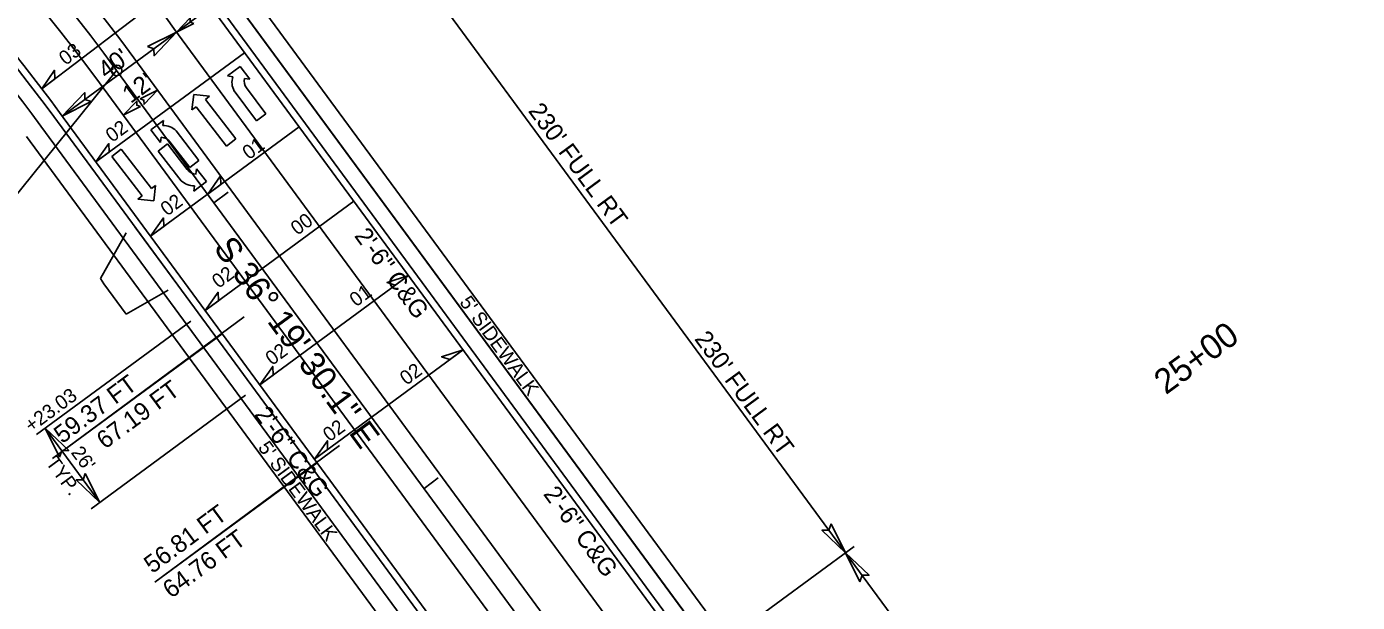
# Model space of a CAD drawing. Extents: x 1762196 to 1766326, y 709922 to 713142.
# Drawn here: x 1763337.1 to 1763712.3, y 712228.7 to 712391.1 of the extents above; entities that cross this region are included whole.
import ezdxf

# ---------------------------------------------------------------- set-up
doc = ezdxf.new("R2010")
doc.units = 0
for name, color, linetype in [('Old_Level_3', 7, 'Continuous'), ('Old_Level_30', 7, 'Continuous'), ('Pattern 1', 7, 'Continuous'), ('Pattern 2', 7, 'Continuous'), ('Pattern 4', 7, 'Continuous'), ('Prop Conc 2ft 6in Curb and Gutter', 7, 'Continuous'), ('Prop Dimension', 7, 'Continuous'), ('Prop EOT', 7, 'Continuous'), ('Prop Horizontal Alignment', 7, 'Continuous'), ('Prop Horizontal Alignment Direction Label', 7, 'Continuous'), ('Prop Horizontal Alignment Station Label', 7, 'Continuous'), ('Prop Horizontal Alignment Tick Label', 7, 'Continuous'), ('Prop Horizontal Alignment Tick Small', 7, 'Continuous'), ('Prop Lane Arrow CELL', 7, 'Continuous'), ('Prop Lane Lines', 7, 'Continuous'), ('Prop Superelevation  Arrow CELL', 7, 'Continuous'), ('Prop Superelevation Label', 7, 'Continuous'), ('Prop Terminator CELL', 7, 'Continuous')]:
    doc.layers.add(name, color=color, linetype=linetype)

msp = doc.modelspace()

# ---------------------------------------------------------------- linework, layer by layer
at = {"layer": 'Old_Level_3'}
for p, q in [((1763357.91, 712320.04), (1763365.16, 712332.88)), ((1763358.84, 712318.59), (1763357.91, 712320.04)), ((1763365.19, 712309.96), (1763358.84, 712318.59)), ((1763377.03, 712316.74), (1763365.19, 712309.96))]:
    msp.add_line(p, q, dxfattribs=at)
at = {"layer": 'Old_Level_30'}
for p, q in [((1763398.44, 712309.25), (1763344.42, 712269.29)), ((1763392.26, 712304.46), (1763344.42, 712269.29)), ((1763425.28, 712272.97), (1763373.22, 712234.45)), ((1763418.99, 712268.11), (1763373.22, 712234.45))]:
    msp.add_line(p, q, dxfattribs=at)
at = {"layer": 'Pattern 1'}
for p, q in [((1763534.54, 712218.15), (1763397.52, 712404.5)), ((1763845.53, 711677), (1763341.12, 712363.03)), ((1763337.1, 712360.07), (1763843.84, 711670.85))]:
    msp.add_line(p, q, dxfattribs=at)
msp.add_lwpolyline([(1763397.52, 712404.5), (1763393.49, 712401.54), (1763530.51, 712215.18)], dxfattribs=at)
msp.add_arc((1762933.05, 712063), 506.5, 36.325, 67.1495, dxfattribs=at)
at = {"layer": 'Pattern 2'}
for p, q in [((1763393.49, 712401.54), (1763530.51, 712215.18)), ((1763534.54, 712218.15), (1763397.52, 712404.5)), ((1763341.12, 712363.03), (1763845.53, 711677)), ((1763337.1, 712360.07), (1763843.84, 711670.85))]:
    msp.add_line(p, q, dxfattribs=at)
msp.add_arc((1762933.05, 712063), 506.5, 36.325, 67.1495, dxfattribs=at)
at = {"layer": 'Pattern 4'}
msp.add_line((1763379.44, 712318.51), (1763367.57, 712334.66), dxfattribs=at)
at = {"layer": 'Prop Conc 2ft 6in Curb and Gutter'}
for p, q in [((1763389.87, 712398.87), (1763526.88, 712212.52)), ((1763344.75, 712365.7), (1763842.1, 711689.26))]:
    msp.add_line(p, q, dxfattribs=at)
msp.add_arc((1762933.05, 712063), 511, 36.325, 65.7844, dxfattribs=at)
at = {"layer": 'Prop Dimension'}
for p, q in [((1763431.73, 712428.03), (1763567.97, 712242.73)), ((1763389.03, 712396.64), (1763379.36, 712389.53)), ((1763379.36, 712389.53), (1763347.13, 712365.84)), ((1763570.39, 712244.51), (1763527.69, 712213.11)), ((1763567.97, 712242.73), (1763627.21, 712162.16))]:
    msp.add_line(p, q, dxfattribs=at)
at = {"layer": 'Prop EOT'}
for p, q in [((1763388.26, 712397.69), (1763525.27, 712211.33)), ((1763346.36, 712366.89), (1763843.71, 711690.45))]:
    msp.add_line(p, q, dxfattribs=at)
msp.add_arc((1762933.05, 712063), 513, 36.325, 65.7844, dxfattribs=at)
at = {"layer": 'Prop Horizontal Alignment'}
msp.add_line((1763362.47, 712378.73), (1764087.96, 711392.01), dxfattribs=at)
msp.add_arc((1762933.05, 712063), 533, 36.325, 77.7598, dxfattribs=at)
at = {"layer": 'Prop Horizontal Alignment Station Label'}
msp.add_line((1763362.47, 712378.73), (1763237.09, 712223.4), dxfattribs=at)
msp.add_circle((1763362.47, 712378.73), 1.5, dxfattribs=at)
at = {"layer": 'Prop Horizontal Alignment Tick Small'}
for p, q in [((1763389.9, 712341.43), (1763393.93, 712344.39)), ((1763449.14, 712260.86), (1763453.17, 712263.82))]:
    msp.add_line(p, q, dxfattribs=at)
at = {"layer": 'Prop Lane Arrow CELL'}
for p, q in [((1763393.77, 712377.15), (1763397.26, 712379.83)), ((1763397.26, 712379.83), (1763399.99, 712376.25)), ((1763395.24, 712376.94), (1763393.77, 712377.15)), ((1763399.99, 712376.25), (1763398.52, 712376.47)), ((1763383.69, 712367.59), (1763384.22, 712371.97)), ((1763384.22, 712371.97), (1763388.68, 712371.43)), ((1763401.94, 712364.47), (1763395.62, 712372.92)), ((1763399.1, 712373.78), (1763404.58, 712366.45)), ((1763384.88, 712368.5), (1763383.69, 712367.59)), ((1763393.43, 712357.41), (1763384.88, 712368.5)), ((1763388.68, 712371.43), (1763387.49, 712370.52)), ((1763387.49, 712370.52), (1763396.04, 712359.43)), ((1763375.67, 712364.63), (1763372.16, 712361.98)), ((1763375.48, 712363.16), (1763375.67, 712364.63)), ((1763404.58, 712366.45), (1763401.94, 712364.47)), ((1763372.16, 712361.98), (1763374.87, 712358.39)), ((1763385.69, 712353.35), (1763379.25, 712361.71)), ((1763376.81, 712358), (1763374.2, 712355.98)), ((1763374.87, 712358.39), (1763375.06, 712359.86)), ((1763382.4, 712350.75), (1763376.81, 712358)), ((1763377.49, 712358.59), (1763383.08, 712351.34)), ((1763396.04, 712359.43), (1763393.43, 712357.41)), ((1763361.11, 712354.47), (1763363.73, 712356.48)), ((1763369.66, 712343.38), (1763361.11, 712354.47)), ((1763363.73, 712356.48), (1763372.27, 712345.39)), ((1763374.2, 712355.98), (1763380.64, 712347.63)), ((1763383.08, 712351.34), (1763385.69, 712353.35)), ((1763385.02, 712350.94), (1763384.83, 712349.47)), ((1763387.77, 712347.38), (1763385.02, 712350.94)), ((1763372.27, 712345.39), (1763373.46, 712346.31)), ((1763373.46, 712346.31), (1763372.93, 712341.92)), ((1763384.25, 712344.66), (1763387.77, 712347.38)), ((1763384.41, 712346.18), (1763384.25, 712344.66)), ((1763368.47, 712342.46), (1763369.66, 712343.38)), ((1763372.93, 712341.92), (1763368.47, 712342.46))]:
    msp.add_line(p, q, dxfattribs=at)
for centre, radius, start, end in [((1763400.24, 712375.39), 5.25, 162.7976, 208.1093), ((1763401.7, 712375.73), 3.28, 167.1272, 216.7854), ((1763375.64, 712357.92), 5.25, 46.3045, 91.6162), ((1763374.91, 712356.6), 3.27, 37.6284, 87.2866), ((1763385.01, 712352.74), 3.28, 217.6284, 267.2866), ((1763384.28, 712351.42), 5.25, 226.3045, 271.6162)]:
    msp.add_arc(centre, radius, start, end, dxfattribs=at)
at = {"layer": 'Prop Lane Lines'}
for p, q in [((1763378.59, 712390.58), (1763574.84, 712123.66)), ((1763367.31, 712382.29), (1763916.53, 711635.29)), ((1763357.64, 712375.18), (1763906.87, 711628.18))]:
    msp.add_line(p, q, dxfattribs=at)
for radius, end in [(539, 77.7598), (527, 77.7598), (553, 48.0096)]:
    msp.add_arc((1762933.05, 712063), radius, 36.325, end, dxfattribs=at)
at = {"layer": 'Prop Superelevation  Arrow CELL'}
for points in [[(1763341.37, 712373.57), (1763344.93, 712378.79), (1763345.05, 712376.37)], [(1763356.63, 712352.92), (1763360.28, 712358.09), (1763360.35, 712355.66)], [(1763388.14, 712343.82), (1763391.79, 712348.99), (1763391.87, 712346.56)], [(1763372.03, 712331.97), (1763375.68, 712337.14), (1763375.76, 712334.71)], [(1763444.73, 712320.88), (1763438.71, 712318.94), (1763441, 712318.14)], [(1763387.43, 712311.03), (1763391.08, 712316.19), (1763391.16, 712313.77)], [(1763460.13, 712299.93), (1763454.11, 712297.99), (1763456.4, 712297.19)], [(1763402.83, 712290.08), (1763406.48, 712295.24), (1763406.56, 712292.82)], [(1763418.23, 712269.13), (1763421.88, 712274.3), (1763421.96, 712271.87)]]:
    msp.add_lwpolyline(points, close=True, dxfattribs=at)
at = {"layer": 'Prop Superelevation Label'}
for p, q in [((1763382.75, 712405.05), (1763341.37, 712373.57)), ((1763398.52, 712383.72), (1763356.63, 712352.92)), ((1763413.93, 712362.78), (1763372.03, 712331.97)), ((1763429.33, 712341.83), (1763387.43, 712311.03)), ((1763444.73, 712320.88), (1763402.83, 712290.08)), ((1763339.91, 712276.08), (1763383.4, 712308.06)), ((1763460.13, 712299.93), (1763418.23, 712269.13)), ((1763355.31, 712255.14), (1763398.8, 712287.12)), ((1763342.33, 712277.86), (1763357.73, 712256.91))]:
    msp.add_line(p, q, dxfattribs=at)
at = {"layer": 'Prop Terminator CELL'}
for points in [[(1763384.26, 712391.98), (1763379.36, 712389.53), (1763383.17, 712393.52), (1763383.18, 712392.34)], [(1763371.19, 712385.45), (1763379.36, 712389.53), (1763373.02, 712382.88), (1763373, 712384.85)], [(1763355.3, 712369.92), (1763347.13, 712365.84), (1763353.48, 712372.49), (1763353.5, 712370.52)], [(1763369.1, 712370.73), (1763374, 712373.18), (1763370.2, 712369.19), (1763370.19, 712370.37)], [(1763369.24, 712368.52), (1763364.34, 712366.07), (1763368.14, 712370.06), (1763368.16, 712368.88)], [(1763346.41, 712269.69), (1763342.33, 712277.86), (1763348.98, 712271.52), (1763347.01, 712271.5)], [(1763353.64, 712265.08), (1763357.73, 712256.91), (1763351.08, 712263.26), (1763353.05, 712263.28)], [(1763563.89, 712250.9), (1763567.97, 712242.73), (1763561.32, 712249.07), (1763563.29, 712249.09)], [(1763572.05, 712234.56), (1763567.97, 712242.73), (1763574.62, 712236.39), (1763572.65, 712236.37)]]:
    msp.add_lwpolyline(points, close=True, dxfattribs=at)

# ---------------------------------------------------------------- texts
at = {"layer": 'Old_Level_30'}
for s, p in [('59.37 FT', (1763347.15, 712273.32)), ('67.19 FT', (1763359.19, 712271.75)), ('56.81 FT', (1763372.54, 712236.69)), ('64.76 FT', (1763377.84, 712229.67))]:
    msp.add_text(s, height=5, rotation=36.4917, dxfattribs=at).set_placement(p)
at = {"layer": 'Prop Dimension'}
for s, height, rotation, p in [("40'", 5, 36.325, (1763359.56, 712376.1)), ("12'", 5, 36.325, (1763366.44, 712369.25)), ("230' FULL RT", 5, 306.325, (1763478.34, 712367.28)), ('2\'-6" C&G', 5, 306.2561, (1763429.31, 712332.07)), ("5' SIDEWALK", 4, 306.3161, (1763458.98, 712313.32)), ("230' FULL RT", 5, 306.325, (1763525.19, 712302.98)), ('2\'-6" C&G', 5, 306.2561, (1763401.15, 712281.7)), ("5' SIDEWALK", 4, 306.3161, (1763402.15, 712272.35)), ('2\'-6" C&G', 5, 306.2561, (1763482.59, 712259.25))]:
    msp.add_text(s, height=height, rotation=rotation, dxfattribs=at).set_placement(p)
at = {"layer": 'Prop Horizontal Alignment Direction Label'}
msp.add_text('S 36%%d 19\' 30.1" E', height=7, rotation=306.2376, dxfattribs=at).set_placement((1763389.58, 712328.61))
at = {"layer": 'Prop Horizontal Alignment Tick Label'}
msp.add_text('25+00', height=7, rotation=36.325, dxfattribs=at).set_placement((1763658.28, 712287.11))
at = {"layer": 'Prop Superelevation Label'}
for s, rotation, p in [('03', 36.9435, (1763348.09, 712379.99)), ('02', 36.325, (1763361.22, 712358.27)), ('01', 36.325, (1763399.78, 712353.38)), ('02', 36.325, (1763376.7, 712337.49)), ('00', 36.325, (1763413.4, 712332.07)), ('02', 36.325, (1763391.2, 712317.09)), ('01', 36.325, (1763429.99, 712311.9)), ('02', 36.325, (1763406.28, 712295.37)), ('02', 36.325, (1763444.18, 712289.79)), ('+23.03', 36.325, (1763338.41, 712276.48)), ('02', 36.325, (1763422.48, 712273.86)), ('TYP.', 306.325, (1763342.34, 712268.07)), ("26'", 306.325, (1763349.43, 712270.96))]:
    msp.add_text(s, height=4, rotation=rotation, dxfattribs=at).set_placement(p)

doc.saveas('drawing.dxf')
